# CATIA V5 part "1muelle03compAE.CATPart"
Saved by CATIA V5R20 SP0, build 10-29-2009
Part number: 1muelle03compAE
Revision: ANY
Definition: UNKNOWN
Nomenclature: 1muelle03compAE
Source: Unknown
Bounding box of the stored display mesh (mm): x -3.4 to 3.4, y -3.4 to 3.4, z -0.001 to 8.149
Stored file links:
  C:\Users\Utente\Desktop\IO LAVORO\3D X SITO CF\CUMSA\3D files BE\BE 031115\1muelle03compAE.CATPart
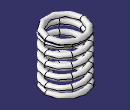
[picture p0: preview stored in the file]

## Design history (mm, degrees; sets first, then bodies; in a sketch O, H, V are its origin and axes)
Set1 "FacciaKO#NONE#4202"
  DatumSurface1 "Sup4202_1"
  DatumCurve1 "Crv4202_1"
Set2 "FacciaKO#NONE#4036"
  DatumSurface2 "Sup4036_1"
  DatumCurve2 "Crv4036_1"
Body1 "Cortar-Extruir1" (main body)
  Solid1: solid without history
